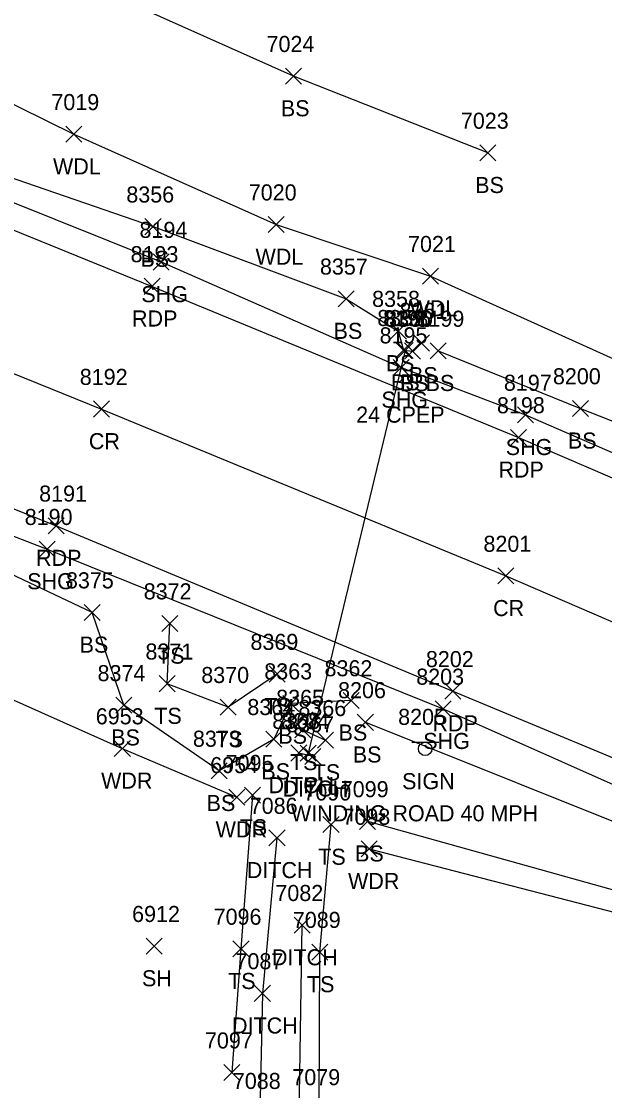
# Model space of a CAD drawing. Extents: x 1588028 to 1589597, y 137576 to 138176.
# Drawn here: x 1589306 to 1589378.5, y 137659.5 to 137792.6 of the extents above; entities that cross this region are included whole.
import ezdxf

# ---------------------------------------------------------------- set-up
doc = ezdxf.new("R2010")
doc.units = 0
for name, color, linetype in [('D_A', 7, 'Continuous'), ('D_C', 7, 'Continuous'), ('D_I', 7, 'Continuous'), ('D_TIC', 7, 'Continuous'), ('DCP', 7, 'Continuous'), ('DD', 7, 'Continuous'), ('L_A', 7, 'Continuous'), ('L_I', 7, 'Continuous'), ('L_TIC', 7, 'Continuous'), ('LAWA', 7, 'Continuous'), ('LELB', 7, 'Continuous'), ('P_A', 7, 'Continuous'), ('P_I', 7, 'Continuous'), ('P_TIC', 7, 'Continuous'), ('PET', 7, 'Continuous'), ('PRC', 7, 'Continuous'), ('PSU', 7, 'Continuous'), ('S_A', 7, 'Continuous'), ('S_C', 7, 'Continuous'), ('S_I', 7, 'Continuous'), ('SSGN', 7, 'Continuous')]:
    doc.layers.add(name, color=color, linetype=linetype)

msp = doc.modelspace()

# ---------------------------------------------------------------- linework, layer by layer
at = {"layer": 'D_TIC'}
for points in [[(1589352.72, 137750.65), (1589354.72, 137752.65)], [(1589354.72, 137750.65), (1589352.72, 137752.65)], [(1589339.48, 137700.54), (1589341.48, 137702.54)], [(1589341.48, 137700.54), (1589339.48, 137702.54)], [(1589340.64, 137700.51), (1589342.64, 137702.51)], [(1589342.64, 137700.51), (1589340.64, 137702.51)], [(1589341.23, 137700.12), (1589343.23, 137702.12)], [(1589343.23, 137700.12), (1589341.23, 137702.12)], [(1589336.77, 137689.97), (1589338.77, 137691.97)], [(1589338.77, 137689.97), (1589336.77, 137691.97)], [(1589339.91, 137679.12), (1589341.91, 137681.12)], [(1589341.91, 137679.12), (1589339.91, 137681.12)], [(1589334.95, 137670.63), (1589336.95, 137672.63)], [(1589336.95, 137670.63), (1589334.95, 137672.63)]]:
    msp.add_lwpolyline(points, dxfattribs=at)
at = {"layer": 'DCP'}
msp.add_lwpolyline([(1589353.72, 137751.65), (1589341.64, 137701.51)], dxfattribs=at)
at = {"layer": 'DD'}
for points in [[(1589342.23, 137701.12), (1589340.48, 137701.54)], [(1589337.77, 137690.97), (1589335.95, 137671.63), (1589335.62, 137656.73)], [(1589340.48, 137653.68), (1589340.91, 137680.12)]]:
    msp.add_lwpolyline(points, dxfattribs=at)
at = {"layer": 'L_TIC'}
for points in [[(1589338.81, 137784.78), (1589340.81, 137786.78)], [(1589340.81, 137784.78), (1589338.81, 137786.78)], [(1589311.49, 137777.55), (1589313.49, 137779.55)], [(1589313.49, 137777.55), (1589311.49, 137779.55)], [(1589362.98, 137775.23), (1589364.98, 137777.23)], [(1589364.98, 137775.23), (1589362.98, 137777.23)], [(1589321.35, 137766.05), (1589323.35, 137768.05)], [(1589323.35, 137766.05), (1589321.35, 137768.05)], [(1589336.68, 137766.31), (1589338.68, 137768.31)], [(1589338.68, 137766.31), (1589336.68, 137768.31)], [(1589355.85, 137759.89), (1589357.85, 137761.89)], [(1589357.85, 137759.89), (1589355.85, 137761.89)], [(1589345.37, 137757.08), (1589347.37, 137759.08)], [(1589347.37, 137757.08), (1589345.37, 137759.08)], [(1589351.86, 137753.06), (1589353.86, 137755.06)], [(1589353.86, 137753.06), (1589351.86, 137755.06)], [(1589354.75, 137751.57), (1589356.75, 137753.57)], [(1589356.75, 137751.57), (1589354.75, 137753.57)], [(1589352.51, 137750.68), (1589354.51, 137752.68)], [(1589354.51, 137750.68), (1589352.51, 137752.68)], [(1589353.61, 137750.57), (1589355.61, 137752.57)], [(1589355.61, 137750.57), (1589353.61, 137752.57)], [(1589356.82, 137750.59), (1589358.82, 137752.59)], [(1589358.82, 137750.59), (1589356.82, 137752.59)], [(1589374.51, 137743.43), (1589376.51, 137745.43)], [(1589376.51, 137743.43), (1589374.51, 137745.43)], [(1589313.78, 137718.03), (1589315.78, 137720.03)], [(1589315.78, 137718.03), (1589313.78, 137720.03)], [(1589323.45, 137716.66), (1589325.45, 137718.66)], [(1589325.45, 137716.66), (1589323.45, 137718.66)], [(1589336.78, 137710.37), (1589338.78, 137712.37)], [(1589338.78, 137710.37), (1589336.78, 137712.37)], [(1589323.11, 137709.17), (1589325.11, 137711.17)], [(1589325.11, 137709.17), (1589323.11, 137711.17)], [(1589317.71, 137706.48), (1589319.71, 137708.48)], [(1589319.71, 137706.48), (1589317.71, 137708.48)], [(1589330.7, 137706.25), (1589332.7, 137708.25)], [(1589332.7, 137706.25), (1589330.7, 137708.25)], [(1589338.5, 137706.7), (1589340.5, 137708.7)], [(1589340.5, 137706.7), (1589338.5, 137708.7)], [(1589345.98, 137707.09), (1589347.98, 137709.09)], [(1589347.98, 137707.09), (1589345.98, 137709.09)], [(1589339.98, 137703.41), (1589341.98, 137705.41)], [(1589341.98, 137703.41), (1589339.98, 137705.41)], [(1589347.76, 137704.36), (1589349.76, 137706.36)], [(1589349.76, 137704.36), (1589347.76, 137706.36)], [(1589336.39, 137702.26), (1589338.39, 137704.26)], [(1589338.39, 137702.26), (1589336.39, 137704.26)], [(1589342.8, 137702.14), (1589344.8, 137704.14)], [(1589344.8, 137702.14), (1589342.8, 137704.14)], [(1589317.53, 137701.11), (1589319.53, 137703.11)], [(1589319.53, 137701.11), (1589317.53, 137703.11)], [(1589329.57, 137698.32), (1589331.57, 137700.32)], [(1589331.57, 137698.32), (1589329.57, 137700.32)], [(1589333.72, 137695.3), (1589335.72, 137697.3)], [(1589335.72, 137695.3), (1589333.72, 137697.3)], [(1589331.78, 137695.04), (1589333.78, 137697.04)], [(1589333.78, 137695.04), (1589331.78, 137697.04)], [(1589343.49, 137691.63), (1589345.49, 137693.63)], [(1589345.49, 137691.63), (1589343.49, 137693.63)], [(1589348.04, 137692.04), (1589350.04, 137694.04)], [(1589350.04, 137692.04), (1589348.04, 137694.04)], [(1589348.24, 137688.61), (1589350.24, 137690.61)], [(1589350.24, 137688.61), (1589348.24, 137690.61)], [(1589321.49, 137676.51), (1589323.49, 137678.51)], [(1589323.49, 137676.51), (1589321.49, 137678.51)], [(1589332.29, 137676.17), (1589334.29, 137678.17)], [(1589334.29, 137676.17), (1589332.29, 137678.17)], [(1589342.09, 137675.77), (1589344.09, 137677.77)], [(1589344.09, 137675.77), (1589342.09, 137677.77)], [(1589331.15, 137660.77), (1589333.15, 137662.77)], [(1589333.15, 137660.77), (1589331.15, 137662.77)]]:
    msp.add_lwpolyline(points, dxfattribs=at)
at = {"layer": 'LAWA'}
for points in [[(1589191.48, 137827.66), (1589208.47, 137821.19), (1589231.01, 137810.22), (1589260.79, 137799.99), (1589288.54, 137790.36), (1589312.49, 137778.55), (1589337.68, 137767.31), (1589356.85, 137760.89), (1589388.23, 137746.7), (1589420.91, 137733.88), (1589453.12, 137717.84), (1589474.94, 137709.38)], [(1589174.22, 137750.28), (1589194.61, 137741.77), (1589225.59, 137739.5), (1589259.02, 137733.29), (1589293.77, 137713.14), (1589318.53, 137702.11), (1589332.78, 137696.04)], [(1589349.24, 137689.61), (1589382.22, 137681.05), (1589414.78, 137667.9), (1589444.95, 137658.35), (1589471.13, 137649.8)]]:
    msp.add_lwpolyline(points, dxfattribs=at)
at = {"layer": 'LELB'}
for points in [[(1589363.98, 137776.23), (1589339.81, 137785.78), (1589298.62, 137804.18), (1589274.05, 137811.91), (1589257.46, 137831.94), (1589243.48, 137848.51), (1589223.01, 137863.17), (1589220.52, 137885.98), (1589218.71, 137913.01)], [(1589158, 137835.46), (1589156.32, 137830.93), (1589175.62, 137825.43), (1589182.94, 137822.51), (1589209.46, 137809.41), (1589234.23, 137800.33), (1589267.46, 137786.74), (1589294.29, 137776.74), (1589322.35, 137767.05), (1589346.37, 137758.08), (1589352.86, 137754.06), (1589353.51, 137751.68), (1589354.61, 137751.57), (1589355.75, 137752.57)], [(1589346.98, 137708.09), (1589339.5, 137707.7), (1589337.39, 137703.26), (1589330.57, 137699.32), (1589318.71, 137707.48), (1589314.78, 137719.03), (1589294.5, 137728.6), (1589257.75, 137742.55), (1589219.17, 137752.77), (1589194.38, 137764.43), (1589173.98, 137767.54)], [(1589357.82, 137751.59), (1589375.51, 137744.43), (1589404.41, 137733.04), (1589436.02, 137719.14), (1589462.97, 137707.98)], [(1589337.78, 137711.37), (1589331.7, 137707.25), (1589324.11, 137710.17), (1589324.45, 137717.66)], [(1589348.76, 137705.36), (1589386.45, 137690.29), (1589418.01, 137675.07), (1589444.66, 137664.76)], [(1589340.98, 137704.41), (1589343.8, 137703.14)], [(1589334.72, 137696.3), (1589333.29, 137677.17), (1589332.15, 137661.77)], [(1589467.95, 137624.31), (1589440.56, 137635.88), (1589398.74, 137645.95), (1589371.69, 137651.72), (1589343.02, 137657.2), (1589343.09, 137676.77), (1589344.49, 137692.63)], [(1589349.04, 137693.04), (1589381.83, 137683.89), (1589416.13, 137670.61), (1589443.9, 137662.06), (1589473.48, 137651.39)]]:
    msp.add_lwpolyline(points, dxfattribs=at)
at = {"layer": 'P_TIC'}
for points in [[(1589322.36, 137761.65), (1589324.36, 137763.65)], [(1589324.36, 137761.65), (1589322.36, 137763.65)], [(1589321.25, 137758.62), (1589323.25, 137760.62)], [(1589323.25, 137758.62), (1589321.25, 137760.62)], [(1589352.23, 137748.52), (1589354.23, 137750.52)], [(1589354.23, 137748.52), (1589352.23, 137750.52)], [(1589314.94, 137743.35), (1589316.94, 137745.35)], [(1589316.94, 137743.35), (1589314.94, 137745.35)], [(1589367.68, 137742.62), (1589369.68, 137744.62)], [(1589369.68, 137742.62), (1589367.68, 137744.62)], [(1589366.82, 137739.82), (1589368.82, 137741.82)], [(1589368.82, 137739.82), (1589366.82, 137741.82)], [(1589309.31, 137728.83), (1589311.31, 137730.83)], [(1589311.31, 137728.83), (1589309.31, 137730.83)], [(1589308.17, 137725.92), (1589310.17, 137727.92)], [(1589310.17, 137725.92), (1589308.17, 137727.92)], [(1589365.22, 137722.58), (1589367.22, 137724.58)], [(1589367.22, 137722.58), (1589365.22, 137724.58)], [(1589358.63, 137708.23), (1589360.63, 137710.23)], [(1589360.63, 137708.23), (1589358.63, 137710.23)], [(1589357.43, 137706.04), (1589359.43, 137708.04)], [(1589359.43, 137706.04), (1589357.43, 137708.04)]]:
    msp.add_lwpolyline(points, dxfattribs=at)
at = {"layer": 'PET'}
for points in [[(1588976.42, 137837.98), (1588964.71, 137855.4), (1588953.74, 137871.46), (1588980.82, 137866.91), (1589021.21, 137859.55), (1589054.58, 137852.92), (1589087.36, 137843.77), (1589127.64, 137831.45), (1589150.05, 137824.37), (1589196.14, 137808.72), (1589243.87, 137790.96), (1589276.87, 137778.08), (1589322.25, 137759.62), (1589367.82, 137740.82), (1589401.87, 137726.11), (1589432.81, 137712.85), (1589459.76, 137701.46)], [(1588976.42, 137837.98), (1589015.38, 137829.77), (1589047.77, 137821.87), (1589087.62, 137811.07), (1589117.34, 137801.67), (1589165.82, 137785.25), (1589185.23, 137778.17), (1589232.28, 137760.8), (1589265.32, 137747.81), (1589310.31, 137729.83), (1589359.63, 137709.23), (1589389.55, 137696.8), (1589422.31, 137682.69), (1589446.91, 137672.54)]]:
    msp.add_lwpolyline(points, dxfattribs=at)
at = {"layer": 'PRC'}
msp.add_lwpolyline([(1588964.71, 137855.4), (1588980.14, 137852.51), (1589018.19, 137844.35), (1589051.57, 137836.27), (1589092.27, 137825.07), (1589122.68, 137816.23), (1589170.7, 137800.29), (1589190.72, 137793.38), (1589238.44, 137775.62), (1589271.31, 137762.4), (1589315.94, 137744.35), (1589366.22, 137723.58), (1589395.71, 137710.87), (1589428.18, 137697.42), (1589453.33, 137686.42)], dxfattribs=at)
at = {"layer": 'PSU'}
for points in [[(1589152.74, 137827.96), (1589197.07, 137811.88), (1589244.81, 137793.79), (1589277.33, 137781.11), (1589323.36, 137762.65), (1589353.23, 137749.52), (1589368.68, 137743.62), (1589402.84, 137728.77), (1589433.2, 137714.7), (1589460.72, 137703.44)], [(1589136.35, 137790.83), (1589164.04, 137781.22), (1589184.55, 137774.07), (1589230.78, 137756.58), (1589263.84, 137744.47), (1589309.17, 137726.92), (1589358.43, 137707.04), (1589387.87, 137693.92), (1589420.52, 137679.79), (1589445.83, 137669.38)]]:
    msp.add_lwpolyline(points, dxfattribs=at)
at = {"layer": 'SSGN'}
for p, q in [((1589354.55, 137702.89), (1589357.88, 137702.89)), ((1589356.2, 137702.06), (1589356.2, 137702.06))]:
    msp.add_line(p, q, dxfattribs=at)
msp.add_circle((1589356.2, 137702.06), 0.833, dxfattribs=at)

# ---------------------------------------------------------------- texts
at = {"layer": 'D_A'}
for s, p in [('P', (1589353.1, 137746.65)), ('DITCH', (1589336.72, 137696.54)), ('DITCH', (1589338.46, 137696.12)), ('P', (1589341.02, 137696.51)), ('DITCH', (1589334.01, 137685.97)), ('DITCH', (1589337.14, 137675.12)), ('DITCH', (1589332.18, 137666.63))]:
    msp.add_text(s, height=2, dxfattribs=at).set_placement(p)
at = {"layer": 'D_C'}
msp.add_text('24 CPEP', height=2, dxfattribs=at).set_placement((1589347.62, 137742.65))
at = {"layer": 'D_I'}
for s, p in [('8196', (1589350.97, 137754.65)), ('8368', (1589337.18, 137704.54)), ('8204', (1589338.3, 137704.51)), ('8367', (1589338.92, 137704.12)), ('7086', (1589334.38, 137693.97)), ('7082', (1589337.57, 137683.12)), ('7087', (1589332.61, 137674.63)), ('7088', (1589332.28, 137659.73))]:
    msp.add_text(s, height=2, dxfattribs=at).set_placement(p)
at = {"layer": 'L_A'}
for s, p in [('BS', (1589338.25, 137780.78)), ('WDL', (1589309.91, 137773.55)), ('BS', (1589362.42, 137771.23)), ('BS', (1589320.79, 137762.05)), ('WDL', (1589335.1, 137762.31)), ('WDL', (1589354.26, 137755.89)), ('BS', (1589344.81, 137753.08)), ('BS', (1589351.3, 137749.06)), ('BS', (1589354.19, 137747.57)), ('BS', (1589351.95, 137746.68)), ('BS', (1589353.05, 137746.57)), ('BS', (1589356.26, 137746.59)), ('BS', (1589373.95, 137739.43)), ('BS', (1589313.22, 137714.03)), ('TS', (1589322.85, 137712.66)), ('TS', (1589336.19, 137706.37)), ('TS', (1589322.51, 137705.17)), ('BS', (1589317.15, 137702.48)), ('TS', (1589330.11, 137702.25)), ('BS', (1589337.94, 137702.7)), ('BS', (1589345.43, 137703.09)), ('TS', (1589339.39, 137699.41)), ('BS', (1589347.2, 137700.36)), ('BS', (1589335.83, 137698.26)), ('TS', (1589342.21, 137698.14)), ('WDR', (1589315.89, 137697.11)), ('BS', (1589329.02, 137694.32)), ('TS', (1589333.13, 137691.3)), ('WDR', (1589330.14, 137691.04)), ('TS', (1589342.9, 137687.63)), ('BS', (1589347.48, 137688.04)), ('WDR', (1589346.61, 137684.61)), ('SH', (1589320.98, 137672.51)), ('TS', (1589331.69, 137672.17)), ('TS', (1589341.5, 137671.77))]:
    msp.add_text(s, height=2, dxfattribs=at).set_placement(p)
at = {"layer": 'L_I'}
for s, p in [('7024', (1589336.47, 137788.78)), ('7019', (1589309.71, 137781.55)), ('7023', (1589360.64, 137779.23)), ('8356', (1589319.03, 137770.05)), ('7020', (1589334.26, 137770.31)), ('7021', (1589354.07, 137763.89)), ('8357', (1589343.11, 137761.08)), ('8358', (1589349.6, 137757.06)), ('8361', (1589353.01, 137755.57)), ('8359', (1589350.24, 137754.68)), ('8360', (1589351.22, 137754.57)), ('8199', (1589355.12, 137754.59)), ('8200', (1589372.09, 137747.43)), ('8375', (1589311.52, 137722.03)), ('8372', (1589321.19, 137720.66)), ('8369', (1589334.47, 137714.37)), ('8371', (1589321.41, 137713.17)), ('8374', (1589315.45, 137710.48)), ('8370', (1589328.35, 137710.25)), ('8363', (1589336.19, 137710.7)), ('8362', (1589343.68, 137711.09)), ('8365', (1589337.67, 137707.41)), ('8206', (1589345.37, 137708.36)), ('8364', (1589334.08, 137706.26)), ('8366', (1589340.43, 137706.14)), ('6953', (1589315.23, 137705.11)), ('8373', (1589327.31, 137702.32)), ('7095', (1589331.38, 137699.3)), ('6954', (1589329.47, 137699.04)), ('7090', (1589341.06, 137695.63)), ('7099', (1589345.7, 137696.04)), ('7098', (1589345.91, 137692.61)), ('6912', (1589319.75, 137680.51)), ('7096', (1589329.89, 137680.17)), ('7089', (1589339.74, 137679.77)), ('7097', (1589328.81, 137664.77)), ('7079', (1589339.68, 137660.2))]:
    msp.add_text(s, height=2, dxfattribs=at).set_placement(p)
at = {"layer": 'P_A'}
for s, p in [('SHG', (1589320.9, 137757.65)), ('RDP', (1589319.74, 137754.62)), ('SHG', (1589350.76, 137744.52)), ('CR', (1589314.37, 137739.35)), ('SHG', (1589366.22, 137738.62)), ('RDP', (1589365.31, 137735.82)), ('RDP', (1589307.8, 137724.83)), ('SHG', (1589306.7, 137721.92)), ('CR', (1589364.65, 137718.58)), ('RDP', (1589357.11, 137704.23)), ('SHG', (1589355.96, 137702.04))]:
    msp.add_text(s, height=2, dxfattribs=at).set_placement(p)
at = {"layer": 'P_I'}
for s, p in [('8194', (1589320.67, 137765.65)), ('8193', (1589319.56, 137762.62)), ('8195', (1589350.53, 137752.52)), ('8192', (1589313.24, 137747.35)), ('8197', (1589365.99, 137746.62)), ('8198', (1589365.13, 137743.82)), ('8191', (1589308.19, 137732.83)), ('8190', (1589306.39, 137729.92)), ('8201', (1589363.45, 137726.58)), ('8202', (1589356.29, 137712.23)), ('8203', (1589355.09, 137710.04))]:
    msp.add_text(s, height=2, dxfattribs=at).set_placement(p)
at = {"layer": 'S_A'}
msp.add_text('SIGN', height=2, dxfattribs=at).set_placement((1589353.33, 137697.04))
at = {"layer": 'S_C'}
msp.add_text('WINDING ROAD 40 MPH', height=2, dxfattribs=at).set_placement((1589339.5, 137693.04))
at = {"layer": 'S_I'}
msp.add_text('8205', height=2, dxfattribs=at).set_placement((1589352.84, 137705.04))

doc.saveas('drawing.dxf')
